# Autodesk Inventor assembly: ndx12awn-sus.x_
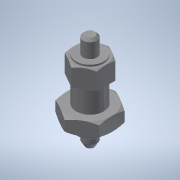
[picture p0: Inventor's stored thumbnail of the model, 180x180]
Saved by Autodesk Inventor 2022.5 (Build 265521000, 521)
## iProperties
Part Number: ndx12awn-sus.x_
Material: 一般
Document SubType Name: Assembly
Designer: ImaoCorp
Sending System: SOLIDWORKS 2017-2017317
MC: AMD64
MC_MODEL: Intel64 Family 6 Model 60 Stepping 3, GenuineIntel
OS: Windows_NT
FRU: Parasolid Version 29.0, build 201,  4-17-2017
FORMAT: text
GUISE: transmit
KEY: ndx12awn-sus
FILE: ndx12awn-sus.x_t
DATE: Wed Sep 04 15:31:16 2019
Author: ImaoCorp
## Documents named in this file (3)
- X:\14_SW2022-Inv2022\00_全2023-1023新製品(TCC)まで\n\ndx12awn-sus\NDX12AWN-SUS.iam
- X:\14_SW2022-Inv2022\00_全2023-1023新製品(TCC)まで\n\ndx12awn-sus\ndx12awn-sus_01.ipt
- X:\14_SW2022-Inv2022\00_全2023-1023新製品(TCC)まで\n\ndx12awn-sus\ndx12awn-sus_02.ipt
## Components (2 placed, 2 different names)
1. ndx12awn-sus_01
2. ndx12awn-sus_02
